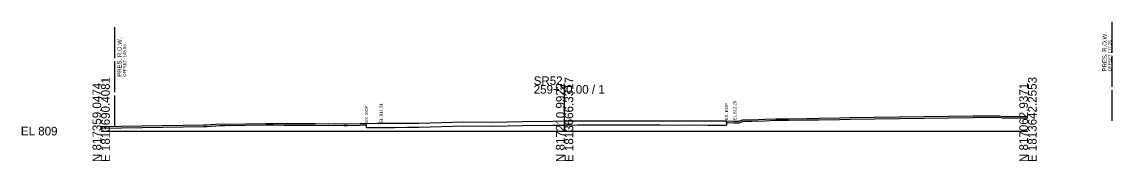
# Model space of a CAD drawing. Extents: x -50 to 1838305, y -27 to 820775.
# Drawn here: x 2974.3 to 3327.3, y 990.3 to 1035.3 of the extents above; entities that cross this region are included whole.
import ezdxf

# ---------------------------------------------------------------- set-up
doc = ezdxf.new("R2010")
doc.units = 0
for name, color, linetype in [('DESIGN - SHEET - Light Grid', 7, 'Continuous'), ('SURVEY - GROUND - Bottom of Topsoil Layer', 7, 'Continuous'), ('SURVEY - GROUND - Existing Pavement Layer', 7, 'Continuous'), ('SURVEY - GROUND - Existing Pavement Text', 7, 'Continuous'), ('SURVEY - GROUND - Top of Ground', 7, 'Continuous'), ('SURVEY - PROPERTY - ROW Lines', 7, 'Continuous'), ('SURVEY - PROPERTY - ROW Lines Text', 7, 'Continuous')]:
    doc.layers.add(name, color=color, linetype=linetype)

msp = doc.modelspace()

# ---------------------------------------------------------------- linework, layer by layer
at = {"layer": 'DESIGN - SHEET - Light Grid'}
for p, q in [((3150, 1000), (3150, 1014.88)), ((3000, 1000), (3150, 1000)), ((3150, 1000), (3300, 1000))]:
    msp.add_line(p, q, dxfattribs=at)
at = {"layer": 'SURVEY - GROUND - Bottom of Topsoil Layer'}
for p, q in [((3085.89, 1002.01), (3085.89, 1002.51)), ((3202.4, 1002.79), (3202.4, 1003.29)), ((3202.4, 1002.79), (3202.55, 1002.79)), ((3202.55, 1002.79), (3204.78, 1002.71)), ((3204.78, 1002.71), (3206.37, 1002.68)), ((3206.37, 1002.68), (3206.73, 1002.83)), ((3206.73, 1002.83), (3207.61, 1003.13)), ((3207.61, 1003.13), (3210.65, 1003.18)), ((3210.65, 1003.18), (3214.83, 1003.32)), ((3214.83, 1003.32), (3218.41, 1003.49)), ((3218.41, 1003.49), (3222.46, 1003.51)), ((3222.46, 1003.51), (3228.44, 1003.62)), ((3228.44, 1003.62), (3232.3, 1003.64)), ((3232.3, 1003.64), (3239, 1003.8)), ((3239, 1003.8), (3242.44, 1003.89)), ((3242.44, 1003.89), (3282.25, 1004.43)), ((3282.25, 1004.43), (3290.76, 1004.46)), ((3290.76, 1004.46), (3291.74, 1004.27)), ((3291.74, 1004.27), (3300, 1004.21)), ((3000, 1000.98), (3033.15, 1001.49)), ((3033.15, 1001.49), (3034.18, 1001.51)), ((3034.18, 1001.51), (3038.5, 1001.83)), ((3038.5, 1001.83), (3039.97, 1001.78)), ((3039.97, 1001.78), (3053.31, 1002)), ((3053.31, 1002), (3055.79, 1001.99)), ((3055.79, 1001.99), (3059.2, 1001.94)), ((3059.2, 1001.94), (3069.25, 1001.94)), ((3069.25, 1001.94), (3073.46, 1001.82)), ((3073.46, 1001.82), (3075.65, 1001.97)), ((3075.65, 1001.97), (3078.56, 1001.81)), ((3078.56, 1001.81), (3079.06, 1001.81)), ((3079.06, 1001.81), (3079.67, 1001.83)), ((3079.67, 1001.83), (3083.78, 1001.96)), ((3083.78, 1001.96), (3085.57, 1002.01)), ((3085.57, 1002.01), (3085.89, 1002.01))]:
    msp.add_line(p, q, dxfattribs=at)
at = {"layer": 'SURVEY - GROUND - Existing Pavement Layer'}
for p, q in [((3085.89, 1001.17), (3085.89, 1002.51)), ((3202.4, 1003.29), (3202.4, 1001.95)), ((3085.89, 1001.17), (3089.44, 1001.18)), ((3089.44, 1001.18), (3090.03, 1001.18)), ((3090.03, 1001.18), (3095.06, 1001.21)), ((3095.06, 1001.21), (3099.04, 1001.24)), ((3099.04, 1001.24), (3099.65, 1001.26)), ((3099.65, 1001.26), (3102.87, 1001.25)), ((3102.87, 1001.25), (3117.34, 1001.67)), ((3117.34, 1001.67), (3126.5, 1001.56)), ((3126.5, 1001.56), (3136.45, 1001.78)), ((3136.45, 1001.78), (3146.16, 1001.88)), ((3146.16, 1001.88), (3150, 1001.94)), ((3150, 1001.94), (3150.54, 1001.95)), ((3150.54, 1001.95), (3154.23, 1001.98)), ((3154.23, 1001.98), (3156.37, 1001.99)), ((3156.37, 1001.99), (3180.89, 1002.03)), ((3180.89, 1002.03), (3186.3, 1001.93)), ((3186.3, 1001.93), (3192.25, 1001.99)), ((3192.25, 1001.99), (3196.49, 1001.96)), ((3196.49, 1001.96), (3198.44, 1001.93)), ((3198.44, 1001.93), (3202.4, 1001.95))]:
    msp.add_line(p, q, dxfattribs=at)
at = {"layer": 'SURVEY - GROUND - Top of Ground'}
msp.add_lwpolyline([(3000, 1001.48), (3033.15, 1001.99), (3034.18, 1002.01), (3038.5, 1002.33), (3039.97, 1002.28), (3053.31, 1002.5), (3055.79, 1002.49), (3059.2, 1002.44), (3069.25, 1002.44), (3073.46, 1002.32), (3075.65, 1002.47), (3078.56, 1002.31), (3079.06, 1002.31), (3079.67, 1002.33), (3083.78, 1002.46), (3085.57, 1002.51), (3089.44, 1002.52), (3090.03, 1002.52), (3095.06, 1002.55), (3099.04, 1002.58), (3099.65, 1002.6), (3102.87, 1002.59), (3117.34, 1003.01), (3126.5, 1002.9), (3136.45, 1003.12), (3146.16, 1003.22), (3150, 1003.28), (3150.54, 1003.29), (3154.23, 1003.32), (3156.37, 1003.33), (3180.89, 1003.37), (3186.3, 1003.27), (3192.25, 1003.33), (3196.49, 1003.3), (3198.44, 1003.27), (3202.55, 1003.29), (3204.78, 1003.21), (3206.37, 1003.18), (3206.73, 1003.33), (3207.61, 1003.63), (3210.65, 1003.68), (3214.83, 1003.82), (3218.41, 1003.99), (3222.46, 1004.01), (3228.44, 1004.12), (3232.3, 1004.14), (3239, 1004.3), (3242.44, 1004.39), (3282.25, 1004.93), (3290.76, 1004.96), (3291.74, 1004.77), (3300, 1004.71)], dxfattribs=at)
at = {"layer": 'SURVEY - PROPERTY - ROW Lines'}
for p, q in [((3327.26, 1025.28), (3327.26, 1035.28)), ((3004.44, 1023.54), (3004.44, 1033.54)), ((3327.26, 1014.28), (3327.26, 1024.28)), ((3004.44, 1012.54), (3004.44, 1022.54)), ((3327.26, 1003.28), (3327.26, 1013.28)), ((3004.44, 1001.54), (3004.44, 1011.54))]:
    msp.add_line(p, q, dxfattribs=at)

# ---------------------------------------------------------------- texts
at = {"layer": 'DESIGN - SHEET - Light Grid'}
for s, p in [('E 1813690.4081', (3002.8, 990)), ('E 1813666.3317', (3152.8, 990)), ('E 1813642.2553', (3302.8, 990)), ('N 817359.0474', (3000, 990)), ('N 817210.9922', (3150, 990)), ('N 817062.9371', (3300, 990))]:
    msp.add_text(s, height=2.8, rotation=90, dxfattribs=at).set_placement(p)
for s, p in [('SR52', (3140, 1014.88)), ('259+50.00 / 1', (3140, 1012.08)), ('EL 809', (2974, 998.6))]:
    msp.add_text(s, height=2.8, dxfattribs=at).set_placement(p)
at = {"layer": 'SURVEY - GROUND - Existing Pavement Text'}
for s, p in [('EL.812.29', (3205.59, 1003.49)), ('EX. EOP', (3086.39, 1002.71)), ('EL.811.51', (3091.1, 1002.71)), ('EX. EOP', (3202.9, 1003.49))]:
    msp.add_text(s, height=1, rotation=90, dxfattribs=at).set_placement(p)
at = {"layer": 'SURVEY - PROPERTY - ROW Lines Text'}
for s, height, p in [('PRES. R.O.W.', 1.4, (3325.51, 1019.28)), ('PRES. R.O.W.', 1.4, (3006.59, 1017.54)), ('OFFSET -145.56', 1, (3008.09, 1017.54)), ('OFFSET 177.26', 1, (3327.01, 1019.28))]:
    msp.add_text(s, height=height, rotation=90, dxfattribs=at).set_placement(p)

doc.saveas('drawing.dxf')
